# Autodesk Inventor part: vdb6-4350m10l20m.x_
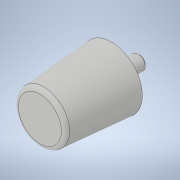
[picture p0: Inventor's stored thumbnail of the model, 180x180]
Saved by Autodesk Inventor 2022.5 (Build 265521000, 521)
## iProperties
Created: 2021-08
Part Number: vdb6-4350m10l20m.x_
Material: 一般
Document SubType Name: Modeling
Designer: ImaoCorp
Density: 1 g/cm^3
Appearance: 既定
Sending System: SOLIDWORKS 2019-2019304
MC: AMD64
MC_MODEL: Intel64 Family 6 Model 60 Stepping 3, GenuineIntel
OS: Windows_NT
FRU: Parasolid Version 31.0, build 290,  9- 1-2019
FORMAT: text
GUISE: transmit
KEY: vdb6-4350m10l20m
FILE: vdb6-4350m10l20m.x_t
DATE: Wed Aug 11 15:00:09 2021
Author: ImaoCorp
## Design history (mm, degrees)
feature "Base1"
node "ソリッド1"
